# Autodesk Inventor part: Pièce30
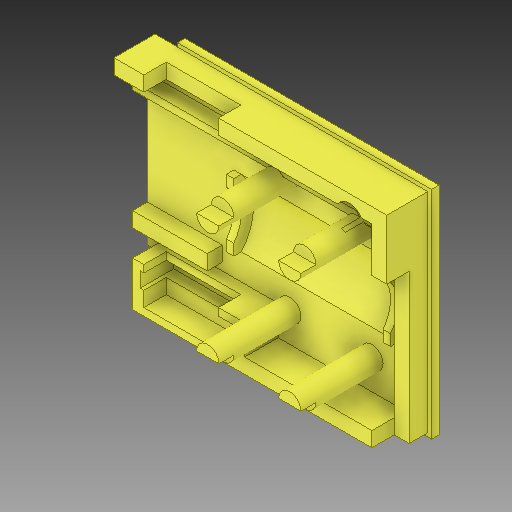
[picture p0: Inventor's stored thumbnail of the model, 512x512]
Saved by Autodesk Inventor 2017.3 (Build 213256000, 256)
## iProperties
Created: 2007-12
Part Number: Pièce30
Material: Générique
Document SubType Name: Modeling
Designer: ficho
Density: 1 g/cm^3
Appearance: Par défaut
Author: ficho
Sending System: SolidWorks 2009
Last Author: christophe
Last Saved: 2011-02-10
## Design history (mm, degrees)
feature "Enlèv. mat.-Extru.11"
node "Solide1"
